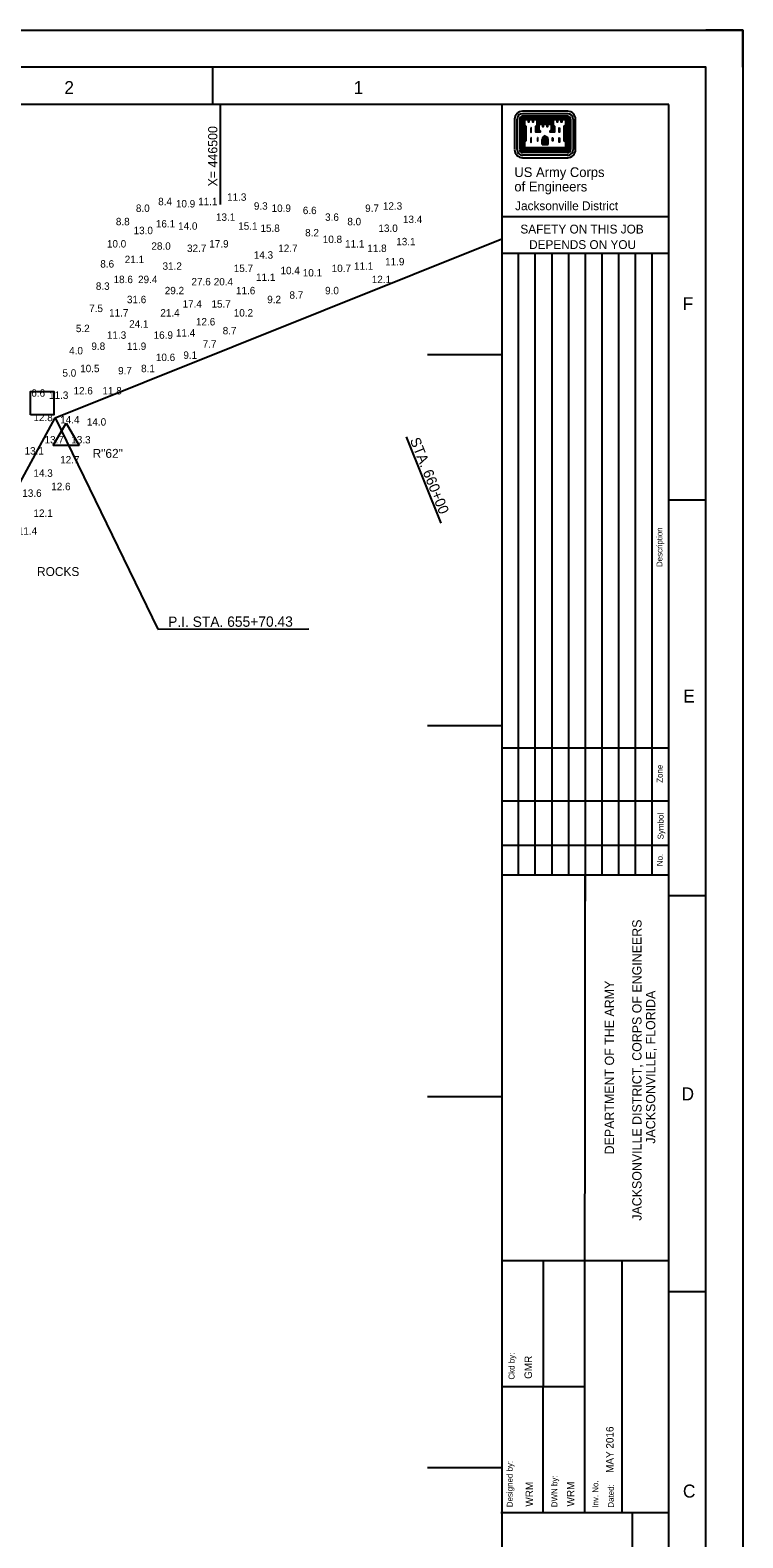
# Model space of a CAD drawing. Extents: x 442804 to 447204, y 1614037 to 1617437.
# Drawn here: x 446244 to 447204, y 1615405 to 1617437 of the extents above; entities that cross this region are included whole.
import ezdxf

# ---------------------------------------------------------------- set-up
doc = ezdxf.new("R2010")
doc.units = 0
for name, color, linetype in [('Default', 7, 'Continuous'), ('G-ANNO-NPLT', 7, 'Continuous'), ('G-ANNO-TEXT-DRWG', 7, 'Continuous'), ('G-ANNO-TEXT-LOGO', 7, 'Continuous'), ('G-ANNO-TEXT-PROJ', 7, 'Continuous'), ('G-ANNO-TEXT-TTLB', 7, 'Continuous'), ('G-ANNO-TTLB', 7, 'Continuous'), ('V-ALGN-TEXT', 7, 'Continuous'), ('V-CHAN-CNTR', 7, 'Continuous'), ('V-CHAN-NAID', 7, 'Continuous'), ('V-TOPO-COOR-STAT', 7, 'Continuous')]:
    doc.layers.add(name, color=color, linetype=linetype)

msp = doc.modelspace()

# ---------------------------------------------------------------- linework, layer by layer
at = {"layer": 'G-ANNO-NPLT'}
msp.add_lwpolyline([(442804.3, 1617437.2), (447204.3, 1617437.2), (447204.3, 1614037.3), (442804.3, 1614037.3)], close=True, dxfattribs=at)
msp.add_lwpolyline([(447204.3, 1617387.2), (447204.3, 1617437.2), (447154.3, 1617437.2)], dxfattribs=at)
at = {"layer": 'G-ANNO-TEXT-LOGO'}
for p, q in [((446968.2, 1617327.9), (446907.4, 1617327.9)), ((446907.4, 1617324.7), (446968.2, 1617324.7)), ((446968.2, 1617321.3), (446907.4, 1617321.3)), ((446968.2, 1617320.4), (446907.4, 1617320.4)), ((446896.7, 1617317.2), (446896.7, 1617276.2)), ((446899.9, 1617276.2), (446899.9, 1617317.2)), ((446903.4, 1617317.2), (446903.4, 1617276.2)), ((446904.3, 1617317.2), (446904.3, 1617276.2)), ((446905.1, 1617317.2), (446905.1, 1617276.2)), ((446906, 1617317.2), (446906, 1617276.2)), ((446906.9, 1617317.2), (446906.9, 1617276.2)), ((446968.2, 1617319.5), (446907.4, 1617319.5)), ((446968.2, 1617318.7), (446907.4, 1617318.7)), ((446968.2, 1617317.8), (446907.4, 1617317.8)), ((446907.8, 1617317.2), (446907.8, 1617276.5)), ((446908.6, 1617317.2), (446908.6, 1617277.4)), ((446909.3, 1617308.5), (446909.3, 1617287.5)), ((446910.2, 1617307.6), (446910.2, 1617288.5)), ((446928.5, 1617317), (446947.1, 1617317)), ((446928.5, 1617316.1), (446947.1, 1617316.1)), ((446928.5, 1617315.3), (446947.1, 1617315.3)), ((446928.5, 1617314.4), (446947.1, 1617314.4)), ((446928.5, 1617313.5), (446947.1, 1617313.5)), ((446928.5, 1617312.7), (446947.1, 1617312.7)), ((446928.5, 1617311.8), (446947.1, 1617311.8)), ((446965.4, 1617307.6), (446965.4, 1617288.5)), ((446966.3, 1617308.4), (446966.3, 1617287.6)), ((446967, 1617317.2), (446967, 1617277.4)), ((446967.8, 1617317.2), (446967.8, 1617276.5)), ((446968.7, 1617317.2), (446968.7, 1617276.2)), ((446969.6, 1617317.2), (446969.6, 1617276.2)), ((446970.4, 1617317.2), (446970.4, 1617276.2)), ((446971.3, 1617317.2), (446971.3, 1617276.2)), ((446972.2, 1617317.2), (446972.2, 1617276.2)), ((446975.6, 1617317.2), (446975.6, 1617276.2)), ((446978.9, 1617276.2), (446978.9, 1617317.2)), ((446933.8, 1617283.3), (446933.8, 1617290)), ((446933.8, 1617283.3), (446941.8, 1617283.3)), ((446934.6, 1617283.3), (446934.6, 1617290)), ((446935.5, 1617283.3), (446935.5, 1617290)), ((446936.4, 1617283.3), (446936.4, 1617290)), ((446937.2, 1617283.3), (446937.2, 1617290)), ((446938.4, 1617283.3), (446938.4, 1617290)), ((446939.2, 1617283.3), (446939.2, 1617290)), ((446940.1, 1617283.3), (446940.1, 1617290)), ((446941, 1617283.3), (446941, 1617290)), ((446941.8, 1617283.3), (446941.8, 1617290)), ((446968.2, 1617275.6), (446907.4, 1617275.6)), ((446968.2, 1617274.8), (446907.4, 1617274.8)), ((446968.2, 1617273.9), (446907.4, 1617273.9)), ((446968.2, 1617273), (446907.4, 1617273)), ((446968.2, 1617272.2), (446907.4, 1617272.2)), ((446968.2, 1617268.7), (446907.4, 1617268.7)), ((446907.4, 1617265.4), (446968.2, 1617265.4)), ((446967.8, 1617276.5), (446907.8, 1617276.5)), ((446967, 1617277.4), (446908.6, 1617277.4))]:
    msp.add_line(p, q, dxfattribs=at)
for points in [[(446909.3, 1617317.2), (446909.3, 1617309.3), (446911, 1617307.6), (446911, 1617288.5), (446909.3, 1617286.7), (446909.3, 1617278), (446966.3, 1617278), (446966.3, 1617286.7), (446964.5, 1617288.5), (446964.5, 1617307.6), (446966.3, 1617309.3), (446966.3, 1617317.2), (446958.8, 1617317.2), (446953, 1617317.2), (446947.6, 1617317.2), (446947.6, 1617309.3), (446949.5, 1617307.6), (446949.5, 1617300.6), (446945.3, 1617300.6), (446945.3, 1617301.3), (446947.1, 1617303.1), (446947.1, 1617310.9), (446939.6, 1617310.9), (446933.8, 1617310.9), (446928.5, 1617310.9), (446928.5, 1617303.1), (446930.3, 1617301.3), (446930.3, 1617300.6), (446926.1, 1617300.6), (446926.1, 1617307.6), (446927.9, 1617309.3), (446927.9, 1617317.2), (446920.4, 1617317.2), (446914.6, 1617317.2), (446909.3, 1617317.2)], [(446910.1, 1617316.3), (446910.1, 1617309.7), (446911.9, 1617307.9), (446911.9, 1617288.1), (446910.1, 1617286.3), (446910.1, 1617278.9), (446965.5, 1617278.9), (446965.5, 1617286.3), (446963.6, 1617288.1), (446963.6, 1617307.9), (446965.5, 1617309.7), (446965.5, 1617316.3), (446960.1, 1617316.3), (446960.1, 1617313.2), (446959.6, 1617313.2), (446959.6, 1617316.3), (446954.3, 1617316.3), (446954.3, 1617313.2), (446953.9, 1617313.2), (446953.9, 1617316.3), (446948.5, 1617316.3), (446948.5, 1617309.7), (446950.3, 1617307.9), (446950.3, 1617299.8), (446944.5, 1617299.8), (446944.5, 1617301.7), (446946.3, 1617303.5), (446946.3, 1617310.1), (446940.9, 1617310.1), (446940.9, 1617307), (446940.5, 1617307), (446940.5, 1617310.1), (446935.1, 1617310.1), (446935.1, 1617307), (446934.6, 1617307), (446934.6, 1617310.1), (446929.3, 1617310.1), (446929.3, 1617303.5), (446931.1, 1617301.7), (446931.1, 1617299.8), (446925.3, 1617299.8), (446925.3, 1617307.9), (446927.1, 1617309.7), (446927.1, 1617316.3), (446921.8, 1617316.3), (446921.8, 1617313.2), (446921.3, 1617313.2), (446921.3, 1617316.3), (446915.9, 1617316.3), (446915.9, 1617313.2), (446915.5, 1617313.2), (446915.5, 1617316.3), (446910.1, 1617316.3)], [(446918.3, 1617305.6), (446918.3, 1617299.8), (446918.9, 1617299.8), (446918.9, 1617305.6), (446918.3, 1617305.6)], [(446927.5, 1617307.7), (446927, 1617307.2), (446927, 1617301.5), (446928.9, 1617301.5), (446927.6, 1617302.8), (446927.6, 1617307.8)], [(446948.1, 1617307.7), (446948.6, 1617307.2), (446948.6, 1617301.5), (446946.8, 1617301.5), (446948, 1617302.8), (446948, 1617307.8)], [(446957.2, 1617305.6), (446957.2, 1617299.8), (446956.7, 1617299.8), (446956.7, 1617305.6), (446957.2, 1617305.6)], [(446918.3, 1617292.3), (446918.3, 1617286.4), (446918.9, 1617286.4), (446918.9, 1617292.3), (446918.3, 1617292.3)], [(446927.5, 1617292.3), (446927.5, 1617288.2), (446928, 1617288.2), (446928, 1617292.3), (446927.5, 1617292.3)], [(446948.1, 1617292.3), (446948.1, 1617288.2), (446947.6, 1617288.2), (446947.6, 1617292.3), (446948.1, 1617292.3)], [(446957.2, 1617292.3), (446957.2, 1617286.4), (446956.7, 1617286.4), (446956.7, 1617292.3), (446957.2, 1617292.3)]]:
    msp.add_lwpolyline(points, dxfattribs=at)
for centre, major_axis, start_param, end_param in [((446907.4, 1617317.2), (10.7, 0), 1.57078, 3.141576), ((446907.4, 1617317.2), (7.49, 0), 1.57078, 3.141576), ((446907.4, 1617317.2), (4.02, 0), 1.57078, 3.141576), ((446907.4, 1617317.2), (3.15, 0), 1.57078, 3.141576), ((446968.1, 1617317.2), (10.7, 0), 6.283169, 7.853965), ((446968.1, 1617317.2), (7.49, 0), 6.28317, 7.853966), ((446968.1, 1617317.2), (4.02, 0), 6.283169, 7.853965), ((446968.1, 1617317.2), (3.15, 0), 6.283169, 7.853965), ((446907.4, 1617317.2), (2.28, 0), 1.57078, 3.141576), ((446907.4, 1617317.2), (1.41, 0), 1.57078, 3.141576), ((446907.4, 1617317.2), (0.546, 0), 1.57078, 3.141576), ((446968.1, 1617317.2), (2.28, 0), 6.283169, 7.853965), ((446968.1, 1617317.2), (1.41, 0), 6.283169, 7.853965), ((446968.1, 1617317.2), (0.546, 0), 6.283169, 7.853965), ((446939.2, 1617289.5), (-5.55, 0), 4.985832, 6.214359), ((446939.2, 1617289.5), (-4.69, 0), 4.947465, 6.21436), ((446939.2, 1617289.5), (-3.82, 0), 4.947465, 6.21436), ((446939.2, 1617289.5), (-2.95, 0), 4.947465, 6.21436), ((446936.2, 1617289.5), (2.08, 0), 0.068794, 1.335689), ((446936.2, 1617289.5), (2.95, 0), 0.068794, 1.335689), ((446936.2, 1617289.5), (3.82, 0), 0.068795, 1.335689), ((446939.2, 1617289.5), (-2.08, 0), 4.947465, 6.214359), ((446936.2, 1617289.5), (4.69, 0), 0.068795, 1.335689), ((446936.2, 1617289.5), (5.55, 0), 0.068795, 1.29842), ((446907.4, 1617276.1), (-10.7, 0), 6.28317, 7.853966), ((446907.4, 1617276.1), (-7.49, 0), 6.28317, 7.853966), ((446907.4, 1617276.1), (-4.02, 0), 6.28317, 7.853966), ((446907.4, 1617276.1), (-3.15, 0), 6.28317, 7.853966), ((446907.4, 1617276.1), (-2.28, 0), 6.28317, 7.853966), ((446907.4, 1617276.1), (-1.41, 0), 6.28317, 7.853966), ((446907.4, 1617276.1), (-0.546, 0), 6.28317, 7.853966), ((446968.1, 1617276.1), (4.02, 0), 4.712373, 6.28317), ((446968.1, 1617276.1), (3.15, 0), 4.712373, 6.28317), ((446968.1, 1617276.1), (2.28, 0), 4.712373, 6.28317), ((446968.1, 1617276.1), (1.41, 0), 4.712373, 6.28317), ((446968.1, 1617276.1), (0.546, 0), 4.712373, 6.28317), ((446968.1, 1617276.1), (10.7, 0), 4.712373, 6.28317), ((446968.1, 1617276.1), (-7.49, 0), 1.570781, 3.141577)]:
    msp.add_ellipse(centre, major_axis=major_axis, ratio=0.99964, start_param=start_param, end_param=end_param, dxfattribs=at)
at = {"layer": 'G-ANNO-TTLB'}
for p, q in [((446489.3, 1617387.2), (446489.3, 1617337.2)), ((446879.3, 1617337.2), (446879.3, 1614137.3)), ((446879.3, 1617186), (447104.3, 1617186)), ((446878.7, 1617136.9), (447103.7, 1617136.9)), ((446901.6, 1617136.9), (446901.6, 1616299)), ((446924.1, 1617136.9), (446924.1, 1616299)), ((446946.6, 1617136.9), (446946.6, 1616299)), ((446969.1, 1617136.9), (446969.1, 1616299)), ((446991.6, 1617136.9), (446991.6, 1616299)), ((447014.1, 1617136.9), (447014.1, 1616299)), ((447036.6, 1617136.9), (447036.6, 1616299)), ((447059.1, 1617136.9), (447059.1, 1616299)), ((447081.6, 1617136.9), (447081.6, 1616299)), ((447154.3, 1616803.7), (447104.3, 1616803.7)), ((446879.3, 1616470), (447104.3, 1616470)), ((446879.3, 1616398.8), (447104.3, 1616398.8)), ((446879.3, 1616338.8), (447104.3, 1616338.8)), ((446879.3, 1616299), (447104.3, 1616299)), ((446991.1, 1615439.4), (446991.8, 1616299)), ((446991.8, 1616299), (446991.8, 1616263.6)), ((447154.3, 1616270.4), (447104.3, 1616270.4)), ((446878.5, 1615779.1), (447104.3, 1615779.1)), ((446935.2, 1615439.5), (446935.4, 1615779.1)), ((447041.3, 1615779.1), (447041.3, 1615439.4)), ((447154.3, 1615737.1), (447104.3, 1615737.1)), ((446878.5, 1615609.2), (446991.3, 1615609.2)), ((446878.1, 1615439.4), (447104.3, 1615439.4)), ((447055, 1615439.4), (447055, 1615088))]:
    msp.add_line(p, q, dxfattribs=at)
for points in [[(442854.3, 1614087.3), (447154.3, 1614087.3), (447154.3, 1617387.2), (442854.3, 1617387.2)], [(447104.3, 1617337.2), (442979.3, 1617337.2), (442979.3, 1614137.3), (447104.3, 1614137.3)]]:
    msp.add_lwpolyline(points, close=True, dxfattribs=at)
at = {"layer": 'V-ALGN-TEXT'}
for p, q in [((446277.4, 1616914.8), (446415.9, 1616630.2)), ((446750.6, 1616889), (446797.1, 1616772.9)), ((446415.9, 1616630.2), (446619.1, 1616630.5))]:
    msp.add_line(p, q, dxfattribs=at)
at = {"layer": 'V-CHAN-CNTR'}
for p, q in [((446277.4, 1616914.8), (446879.3, 1617156)), ((445679.4, 1615812.8), (446277.4, 1616914.8))]:
    msp.add_line(p, q, dxfattribs=at)
at = {"layer": 'V-CHAN-NAID'}
for p, q in [((446274.7, 1616877.3), (446292.3, 1616907.7)), ((446292.3, 1616907.7), (446309.7, 1616877.5)), ((446309.8, 1616877.3), (446274.7, 1616877.3))]:
    msp.add_line(p, q, dxfattribs=at)
msp.add_lwpolyline([(446244.2, 1616918.9), (446244.2, 1616950.2), (446275.5, 1616950.2), (446275.5, 1616918.9)], close=True, dxfattribs=at)
at = {"layer": 'V-TOPO-COOR-STAT'}
for p, q in [((446500, 1617202.2), (446500, 1617337.2)), ((446779.3, 1617000), (446879.3, 1617000)), ((446779.3, 1616500), (446879.3, 1616500)), ((446779.3, 1616000), (446879.3, 1616000)), ((446779.3, 1615500), (446879.3, 1615500))]:
    msp.add_line(p, q, dxfattribs=at)

# ---------------------------------------------------------------- texts
at = {"layer": 'Default'}
for s, p in [('8.0', (446386.2, 1617192.3)), ('8.4', (446416.2, 1617201.3)), ('10.9 ', (446440.1, 1617198.3)), ('11.1 ', (446470.1, 1617201.3)), ('11.3 ', (446509.1, 1617207.3)), ('9.3', (446545.2, 1617195.3)), ('10.9 ', (446569.1, 1617192.3)), ('6.6', (446611.2, 1617189.3)), ('9.7', (446695.2, 1617192.3)), ('12.3 ', (446719.1, 1617195.3)), ('8.8', (446359.2, 1617174.3)), ('16.1 ', (446413.1, 1617171.3)), ('14.0 ', (446443.1, 1617168.3)), ('13.1 ', (446494.1, 1617180.3)), ('15.1 ', (446524.1, 1617168.3)), ('3.6', (446641.2, 1617180.3)), ('8.0', (446671.2, 1617174.3)), ('13.4 ', (446746.1, 1617177.3)), ('13.0 ', (446383.1, 1617162.3)), ('15.8 ', (446554.1, 1617165.3)), ('8.2', (446614.3, 1617159.3)), ('10.8 ', (446638.1, 1617150.3)), ('13.0 ', (446713.1, 1617165.3)), ('10.0 ', (446347.1, 1617144.3)), ('28.0 ', (446407.1, 1617141.3)), ('32.7 ', (446455.1, 1617138.3)), ('17.9 ', (446485.1, 1617144.3)), ('14.3 ', (446545.1, 1617129.3)), ('12.7 ', (446578.1, 1617138.3)), ('11.1 ', (446668.1, 1617144.3)), ('11.8 ', (446698.1, 1617138.3)), ('13.1 ', (446737.1, 1617147.3)), ('8.6', (446338.2, 1617117.3)), ('21.1 ', (446371.1, 1617123.3)), ('31.2 ', (446422.1, 1617114.3)), ('15.7 ', (446518.1, 1617111.3)), ('10.4 ', (446581.1, 1617108.3)), ('10.7 ', (446650.1, 1617111.3)), ('11.1 ', (446680.1, 1617114.3)), ('11.9 ', (446722.1, 1617120.3)), ('8.3', (446332.2, 1617087.3)), ('18.6 ', (446356.1, 1617096.3)), ('29.4 ', (446389.1, 1617096.3)), ('27.6 ', (446461.1, 1617093.3)), ('20.4 ', (446491.1, 1617093.3)), ('11.1 ', (446548.1, 1617099.3)), ('10.1 ', (446611.1, 1617105.3)), ('12.1 ', (446704.1, 1617096.3)), ('31.6 ', (446374.1, 1617069.3)), ('29.2 ', (446425.1, 1617081.3)), ('11.6 ', (446521.1, 1617081.3)), ('9.2', (446563.2, 1617069.3)), ('8.7', (446593.2, 1617075.3)), ('9.0', (446641.2, 1617081.3)), ('7.5', (446323.2, 1617057.3)), ('11.7 ', (446350.1, 1617051.3)), ('21.4 ', (446419.1, 1617051.3)), ('17.4 ', (446449.1, 1617063.3)), ('15.7 ', (446488.1, 1617063.3)), ('10.2 ', (446518.1, 1617051.3)), ('5.2', (446305.3, 1617030.3)), ('24.1 ', (446377.1, 1617036.3)), ('12.6 ', (446467.1, 1617039.3)), ('8.7', (446503.2, 1617027.3)), ('9.8', (446326.2, 1617006.3)), ('11.3 ', (446347.1, 1617021.3)), ('11.9 ', (446374.1, 1617006.3)), ('16.9 ', (446410.1, 1617021.3)), ('11.4 ', (446440.1, 1617024.3)), ('7.7', (446476.2, 1617009.3)), ('4.0', (446296.2, 1617000.3)), ('10.6 ', (446413.1, 1616991.3)), ('9.1', (446450.2, 1616994.3)), ('5.0', (446287.2, 1616970.3)), ('10.5 ', (446311.1, 1616976.3)), ('9.7', (446362.2, 1616973.3)), ('8.1', (446393.2, 1616976.3)), ('12.6 ', (446302.1, 1616946.3)), ('11.8 ', (446341.1, 1616946.3)), ('6.6', (446245.2, 1616943.3)), ('11.3 ', (446269.1, 1616940.3)), ('12.8 ', (446248.1, 1616910.3)), ('14.4 ', (446284.1, 1616907.3)), ('14.0 ', (446320.1, 1616904.3)), ('13.1 ', (446236.1, 1616865.3)), ('13.7 ', (446263.1, 1616880.3)), ('13.3 ', (446299.1, 1616880.3)), ('12.7 ', (446284.1, 1616853.3)), ('14.3 ', (446248.1, 1616835.3)), ('13.6 ', (446233.1, 1616808.3)), ('12.6 ', (446272.1, 1616817.3)), ('12.1 ', (446248.1, 1616781.3)), ('11.4 ', (446227.1, 1616757.3))]:
    msp.add_text(s, height=10, dxfattribs=at).set_placement(p)
at = {"layer": 'G-ANNO-TEXT-DRWG'}
for s, p in [('GMR', (446920, 1615619.6)), ('WRM', (446921.5, 1615447.5)), ('WRM', (446977.2, 1615447.7))]:
    msp.add_text(s, height=10, rotation=90, dxfattribs=at).set_placement(p)
at = {"layer": 'G-ANNO-TEXT-PROJ'}
msp.add_text('MAY 2016', height=10, rotation=90, dxfattribs=at).set_placement((447030, 1615493))
at = {"layer": 'G-ANNO-TEXT-TTLB'}
for s, height, p in [('US Army Corps', 13.086, (446896.3, 1617239.3)), ('of Engineers', 13.086, (446896.3, 1617219.9)), ('Jacksonville District', 11.9, (446897.3, 1617194.6)), ('SAFETY ON THIS JOB', 11.9, (446904.4, 1617163.2)), ('DEPENDS ON YOU', 11.9, (446916.2, 1617142.3))]:
    msp.add_text(s, height=height, dxfattribs=at).set_placement(p)
for s, height, p in [('Description', 8, (447095.9, 1616713.7)), ('Zone', 8, (447096.2, 1616423)), ('Symbol', 8, (447097.4, 1616346.7)), ('No.', 8, (447096.4, 1616310.6)), ('JACKSONVILLE DISTRICT, CORPS OF ENGINEERS', 12.5, (447067.7, 1615832.8)), ('DEPARTMENT OF THE ARMY', 12.5, (447030.7, 1615922.2)), ('JACKSONVILLE, FLORIDA', 12.5, (447086.2, 1615936.6)), ('Ckd by:', 8, (446896.5, 1615618.7)), ('Designed by:', 8, (446894.1, 1615446.7)), ('DWN by:', 8, (446954.3, 1615446.7)), ('Inv. No.', 8, (447009.5, 1615446)), ('Dated:', 8, (447030.4, 1615446.1))]:
    msp.add_text(s, height=height, rotation=90, dxfattribs=at).set_placement(p)
at = {"layer": 'G-ANNO-TTLB'}
for s, p in [('2', (446289.7, 1617351.1)), ('1', (446679.7, 1617351.1)), ('F', (447123.1, 1617059.9)), ('E', (447123.9, 1616531.1)), ('D', (447121.6, 1615995)), ('C', (447123.5, 1615459.7))]:
    msp.add_text(s, height=17.5, dxfattribs=at).set_placement(p)
at = {"layer": 'V-ALGN-TEXT'}
for s, rotation, p in [('STA. 660+00', 291.8439, (446755.2, 1616885)), ('P.I. STA. 655+70.43', 0.0976, (446429.6, 1616633))]:
    msp.add_text(s, height=13.92, rotation=rotation, dxfattribs=at).set_placement(p)
at = {"layer": 'V-CHAN-NAID'}
for s, p in [('R"62"', (446327.8, 1616860.9)), ('ROCKS', (446252.9, 1616701.6))]:
    msp.add_text(s, height=12, dxfattribs=at).set_placement(p)
at = {"layer": 'V-TOPO-COOR-STAT'}
msp.add_text('X= 446500', height=12.5, rotation=90, dxfattribs=at).set_placement((446496, 1617226.6))

doc.saveas('drawing.dxf')
